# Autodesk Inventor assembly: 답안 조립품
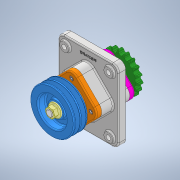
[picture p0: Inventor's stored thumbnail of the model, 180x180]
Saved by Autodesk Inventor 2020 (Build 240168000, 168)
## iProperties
Created: 2021-07
Part Number: 답안 조립품
Document SubType Name: Assembly
Designer: Owner
Author: Owner
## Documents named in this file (16)
- C:\Users\Owner\Desktop\710707V1007\답안 조립품.iam
- C:\Users\Owner\Desktop\710707V1007\본체.ipt
- C:\Users\Owner\Desktop\710707V1007\M16 너트.ipt
- C:\Users\Owner\Desktop\710707V1007\V-벨트풀리.ipt
- C:\Users\Owner\Desktop\710707V1007\멈춤나사 M4.ipt
- C:\Users\Owner\Desktop\710707V1007\베어링 6206.ipt
- C:\Users\Owner\Desktop\710707V1007\볼트 M6.ipt
- C:\Users\Owner\Desktop\710707V1007\부시.ipt
- C:\Users\Owner\Desktop\710707V1007\오일실 30x42x8.ipt
- C:\Users\Owner\Desktop\710707V1007\오일실 30x45x8.ipt
- C:\Users\Owner\Desktop\710707V1007\체인 스프로킷.ipt
- C:\Users\Owner\Desktop\710707V1007\축.ipt
- C:\Users\Owner\Desktop\710707V1007\커버A.ipt
- C:\Users\Owner\Desktop\710707V1007\커버B.ipt
- C:\Users\Owner\Desktop\710707V1007\키 6x6x18.ipt
- C:\Users\Owner\Desktop\710707V1007\키 6x6x20.ipt
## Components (3 placed, 2 different names)
1. M16 너트:1
2. V-벨트풀리:1 — 각도:1
3. M16 너트:2
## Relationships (1: Angle 1)
- 각도:1 [Angle]: V-벨트풀리:1
